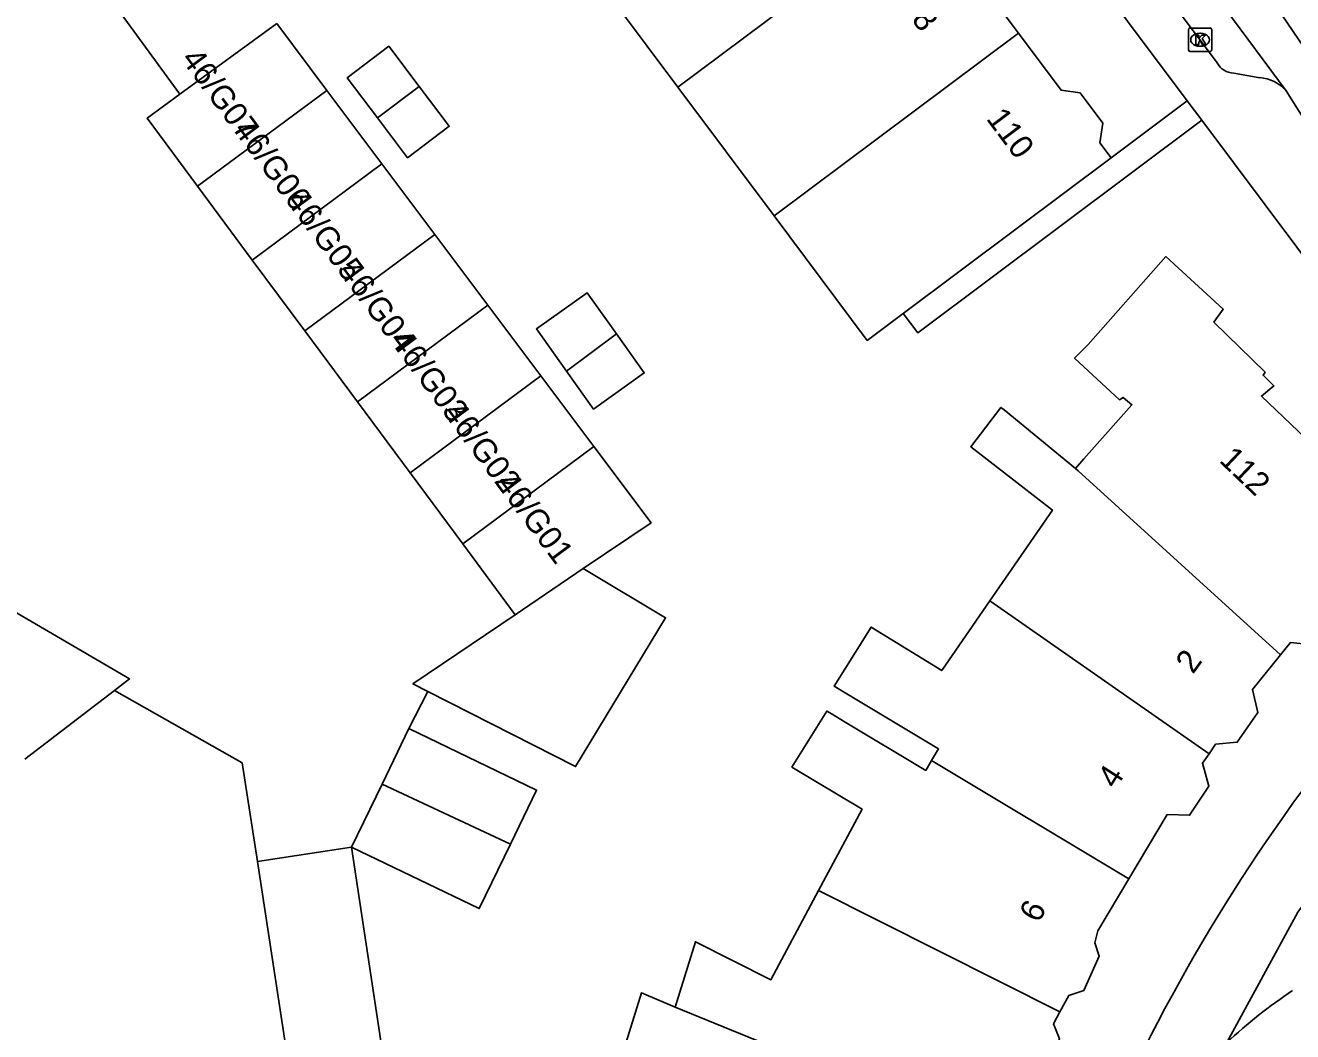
# Model space of a CAD drawing. Extents: x 160356 to 161355, y 381727 to 382845.
# Drawn here: x 161242.7 to 161296.7, y 382411.4 to 382454.3 of the extents above; entities that cross this region are included whole.
import ezdxf

# ---------------------------------------------------------------- set-up
doc = ezdxf.new("R2010")
doc.units = 0
for name, color, linetype in [('IMGEO_Fietspad_gesloten', 7, 'Continuous'), ('IMGEO_Kolk', 7, 'Continuous'), ('IMGEO_Pand', 7, 'Continuous'), ('IMGEO_Pand_nummerreeks', 7, 'Continuous'), ('IMGEO_Rijbaan_lokaal_gesloten', 7, 'Continuous'), ('IMGEO_Rijbaan_lokaal_open', 7, 'Continuous'), ('IMGEO_Voetpad_halfverhard', 7, 'Continuous'), ('IMGEO_Voetpad_open', 7, 'Continuous')]:
    doc.layers.add(name, color=color, linetype=linetype)

msp = doc.modelspace()

# ---------------------------------------------------------------- linework, layer by layer
at = {"layer": 'IMGEO_Fietspad_gesloten'}
msp.add_arc((161309.533, 382394.099), 22.988, 123.9133, 132.8572, dxfattribs=at)
at = {"layer": 'IMGEO_Kolk'}
for p, q in [((161292.264, 382453.23), (161292.264, 382454.082)), ((161292.339, 382454.156), (161293.191, 382454.156)), ((161293.265, 382454.082), (161293.265, 382453.23)), ((161292.752, 382453.936), (161292.777, 382453.936)), ((161293.191, 382453.156), (161292.339, 382453.156)), ((161292.775, 382453.376), (161292.75, 382453.376))]:
    msp.add_line(p, q, dxfattribs=at)
for points in [[(161292.264, 382453.23), (161292.264, 382454.082)], [(161292.339, 382454.156), (161293.191, 382454.156)], [(161293.265, 382454.082), (161293.265, 382453.23)], [(161292.585, 382453.856), (161292.708, 382453.856), (161292.708, 382453.705), (161292.838, 382453.856), (161293.002, 382453.856), (161292.856, 382453.705), (161293.009, 382453.456), (161292.857, 382453.456), (161292.772, 382453.62), (161292.708, 382453.553), (161292.708, 382453.456), (161292.585, 382453.456), (161292.585, 382453.856)], [(161293.191, 382453.156), (161292.339, 382453.156)]]:
    msp.add_lwpolyline(points, dxfattribs=at)
for centre, start, end in [((161292.341, 382454.08), 91.552, 178.448), ((161292.341, 382454.08), 91.552, 178.448), ((161293.189, 382454.08), 1.552, 88.448), ((161293.189, 382454.08), 1.552, 88.448), ((161292.341, 382453.232), 181.552, 268.448), ((161292.341, 382453.232), 181.552, 268.448), ((161293.189, 382453.232), 271.552, 358.448), ((161293.189, 382453.232), 271.552, 358.448)]:
    msp.add_arc(centre, 0.0765, start, end, dxfattribs=at)
for centre, major_axis, ratio, start_param, end_param in [((161292.751, 382453.656), (-0.387, 0.002), 0.722429, 4.712389, 7.853982), ((161292.776, 382453.656), (-0.39, 0.002), 0.717154, 1.570796, 4.712389)]:
    msp.add_ellipse(centre, major_axis=major_axis, ratio=ratio, start_param=start_param, end_param=end_param, dxfattribs=at)
at = {"layer": 'IMGEO_Pand'}
for points in [[(161248.917, 382460.37), (161244.968, 382457.307), (161249.316, 382451.341)], [(161280.868, 382459.375), (161270.521, 382451.639)], [(161280.868, 382459.375), (161281.262, 382458.848), (161282.191, 382458.714), (161283.069, 382457.541), (161283.209, 382456.37), (161285.027, 382453.94)], [(161270.521, 382451.639), (161266.555, 382456.939)], [(161249.316, 382451.341), (161253.437, 382454.344)], [(161253.437, 382454.344), (161255.571, 382451.499)], [(161285.027, 382453.94), (161274.622, 382446.157)], [(161285.027, 382453.94), (161286.844, 382451.512), (161287.651, 382451.396), (161288.619, 382450.103), (161288.499, 382449.269), (161288.977, 382448.629)], [(161257.724, 382450.327), (161256.431, 382452.031), (161258.208, 382453.378), (161259.508, 382451.663)], [(161249.316, 382451.341), (161247.919, 382450.316), (161250.067, 382447.418)], [(161250.067, 382447.418), (161255.571, 382451.499)], [(161255.571, 382451.499), (161257.919, 382448.368)], [(161259.508, 382451.663), (161260.788, 382449.975), (161259.012, 382448.628), (161257.724, 382450.327)], [(161259.508, 382451.663), (161257.724, 382450.327)], [(161274.622, 382446.157), (161270.521, 382451.639)], [(161288.977, 382448.629), (161284.974, 382445.634), (161280.125, 382442.004)], [(161257.919, 382448.368), (161252.398, 382444.275)], [(161257.919, 382448.368), (161260.175, 382445.36)], [(161250.067, 382447.418), (161252.398, 382444.275)], [(161280.125, 382442.004), (161278.589, 382440.855), (161274.622, 382446.157)], [(161254.638, 382441.254), (161260.175, 382445.36)], [(161260.175, 382445.36), (161262.432, 382442.352)], [(161252.398, 382444.275), (161254.638, 382441.254)], [(161287.457, 382435.399), (161287.82, 382435.809), (161289.862, 382438.114), (161289.492, 382438.423), (161289.332, 382438.323), (161287.42, 382440.094), (161287.992, 382440.681), (161291.303, 382444.426), (161293.749, 382442.184), (161293.351, 382441.633), (161295.536, 382439.5), (161295.447, 382439.37), (161295.908, 382438.912), (161295.379, 382438.481), (161299.149, 382434.893), (161298.809, 382434.622), (161300.063, 382433.357), (161300.086, 382432.427), (161298.592, 382430.413), (161298.805, 382429.404), (161297.69, 382427.881), (161296.61, 382427.987), (161296.187, 382427.464)], [(161265.78, 382439.543), (161264.496, 382441.343), (161266.659, 382442.885), (161267.907, 382441.134)], [(161256.878, 382438.234), (161262.432, 382442.352)], [(161262.432, 382442.352), (161264.688, 382439.344)], [(161254.638, 382441.254), (161256.878, 382438.234)], [(161267.907, 382441.134), (161269.093, 382439.47), (161266.931, 382437.928), (161265.78, 382439.543)], [(161265.78, 382439.543), (161267.907, 382441.134)], [(161264.688, 382439.344), (161259.117, 382435.213)], [(161264.688, 382439.344), (161266.944, 382436.336)], [(161256.878, 382438.234), (161259.117, 382435.213)], [(161283.812, 382429.765), (161286.477, 382433.625), (161283, 382436.324), (161284.285, 382437.998), (161284.427, 382437.895), (161287.457, 382435.399)], [(161261.357, 382432.193), (161266.944, 382436.336)], [(161266.944, 382436.336), (161269.381, 382433.087), (161266.495, 382431.134)], [(161259.117, 382435.213), (161261.357, 382432.193)], [(161296.187, 382427.464), (161287.574, 382435.303), (161287.457, 382435.399)], [(161261.357, 382432.193), (161263.597, 382429.172)], [(161266.495, 382431.134), (161269.999, 382429.045), (161266.167, 382422.705), (161259.867, 382425.905)], [(161266.495, 382431.134), (161263.597, 382429.172)], [(161246.532, 382425.946), (161247.171, 382426.437), (161241.351, 382429.839), (161240.633, 382429.288), (161238.956, 382428.001)], [(161281.329, 382422.965), (161281.625, 382423.459), (161277.654, 382425.84), (161277.181, 382426.124), (161278.09, 382427.582), (161278.751, 382428.645), (161281.759, 382426.793), (161283.812, 382429.765)], [(161293.145, 382423.252), (161283.812, 382429.765)], [(161263.597, 382429.172), (161259.24, 382426.224), (161259.867, 382425.905)], [(161296.187, 382427.464), (161294.997, 382425.993), (161295.23, 382425.004), (161294.344, 382423.742), (161293.424, 382423.659), (161293.145, 382423.252)], [(161246.532, 382425.946), (161242.715, 382423.018)], [(161276.516, 382417.426), (161278.369, 382420.894), (161275.381, 382422.685), (161276.865, 382425.07), (161277.091, 382424.935), (161277.576, 382424.644), (161281.077, 382422.545), (161281.329, 382422.965)], [(161259.068, 382424.332), (161257.923, 382421.962)], [(161259.068, 382424.332), (161264.503, 382421.708), (161263.388, 382419.401)], [(161293.145, 382423.252), (161292.867, 382422.847), (161293.14, 382421.879), (161292.314, 382420.636), (161291.364, 382420.663), (161289.734, 382417.927)], [(161281.329, 382422.965), (161289.734, 382417.927)], [(161257.923, 382421.962), (161256.629, 382419.28)], [(161263.388, 382419.401), (161257.923, 382421.962)], [(161263.388, 382419.401), (161262.063, 382416.656), (161256.629, 382419.28)], [(161289.734, 382417.927), (161288.41, 382415.706), (161288.282, 382415.196), (161288.464, 382414.626), (161287.818, 382413.165), (161287.169, 382412.963), (161286.797, 382412.264)], [(161270.404, 382412.467), (161271.272, 382415.248), (161274.489, 382413.632), (161276.516, 382417.426)], [(161286.797, 382412.264), (161276.516, 382417.426)], [(161273.292, 382403.765), (161273.049, 382403.841), (161273.131, 382404.102), (161271.16, 382404.776), (161272.337, 382408.568), (161267.994, 382409.924), (161268.977, 382413.075), (161270.404, 382412.467)], [(161270.404, 382412.467), (161284.629, 382406.663)], [(161286.797, 382412.264), (161286.523, 382411.751), (161286.775, 382411.112), (161286.159, 382409.681), (161285.51, 382409.439), (161285.282, 382409.018), (161285.442, 382408.949), (161284.629, 382406.663)]]:
    msp.add_lwpolyline(points, dxfattribs=at)
at = {"layer": 'IMGEO_Rijbaan_lokaal_gesloten'}
for points in [[(161117.925, 382683.211), (161123.617, 382676.443), (161133.559, 382664.319), (161143.121, 382652.621), (161160.969, 382630.22), (161167.454, 382622.169), (161172.046, 382616.96), (161178.106, 382610.235), (161184.449, 382603.321), (161188.852, 382598.538), (161202.439, 382580.494), (161219.434, 382557.619), (161238.986, 382532.046), (161258.207, 382506.378), (161277.616, 382480.046), (161290.493, 382462.855), (161291.777, 382461.04), (161296.221, 382454.757), (161300.814, 382447.985), (161304.019, 382442.807)], [(161254.544, 382507.935), (161290.179, 382459.912), (161296.429, 382451.481)], [(161296.429, 382451.481), (161297.542, 382449.719)]]:
    msp.add_lwpolyline(points, dxfattribs=at)
at = {"layer": 'IMGEO_Rijbaan_lokaal_open'}
for points in [[(161252.613, 382418.666), (161251.972, 382422.864), (161246.532, 382425.946)], [(161259.867, 382425.905), (161259.068, 382424.332)], [(161256.629, 382419.28), (161252.613, 382418.666)]]:
    msp.add_lwpolyline(points, dxfattribs=at)
at = {"layer": 'IMGEO_Voetpad_halfverhard'}
for points in [[(161256.629, 382419.28), (161258.314, 382408.107)], [(161255.439, 382400.174), (161252.613, 382418.666)]]:
    msp.add_lwpolyline(points, dxfattribs=at)
at = {"layer": 'IMGEO_Voetpad_open'}
for points in [[(161292.218, 382451.055), (161287.175, 382457.792), (161255.578, 382500), (161243.04, 382516.778)], [(161293.496, 382452.678), (161288.802, 382458.94), (161269.626, 382484.519), (161258.072, 382500), (161254.755, 382504.444)], [(161295.304, 382452.041), (161294.198, 382452.238)], [(161288.977, 382448.629), (161292.218, 382451.055)], [(161292.218, 382451.055), (161292.838, 382450.226)], [(161292.838, 382450.226), (161280.745, 382441.175), (161280.125, 382442.004)], [(161306.327, 382432.209), (161292.838, 382450.226)], [(161293.897, 382410.951), (161296.933, 382416.503), (161301.501, 382422.627), (161304.723, 382426.245), (161306.688, 382428.195)]]:
    msp.add_lwpolyline(points, dxfattribs=at)
for centre, radius, start, end in [((161294.196, 382453.015), 0.777, 205.7207, 270.1219), ((161295.198, 382450.419), 1.626, 40.7995, 86.2743), ((161359.336, 382376.008), 77.186, 142.29377, 172.89517)]:
    msp.add_arc(centre, radius, start, end, dxfattribs=at)

# ---------------------------------------------------------------- texts
at = {"layer": 'IMGEO_Pand_nummerreeks'}
for s, rotation, p in [('108', 306.9326, (161279.551, 382455.71)), ('46/G07', 306.5873, (161249.331, 382452.826)), ('110', 306.9326, (161283.627, 382450.287)), ('46/G06', 306.5873, (161251.564, 382449.818)), ('46/G05', 306.5873, (161253.797, 382446.809)), ('46/G04', 306.5873, (161256.03, 382443.801)), ('46/G03', 306.5873, (161258.263, 382440.793)), ('46/G02', 306.5873, (161260.496, 382437.785)), ('112', 316.4151, (161293.536, 382435.707)), ('46/G01', 306.5873, (161262.729, 382434.777)), ('2', 54.156, (161292.461, 382426.608)), ('4', 57.3588, (161289.168, 382421.717)), ('6', 62.5842, (161285.901, 382416.012))]:
    msp.add_text(s, height=1, rotation=rotation, dxfattribs=at).set_placement(p)

doc.saveas('drawing.dxf')
